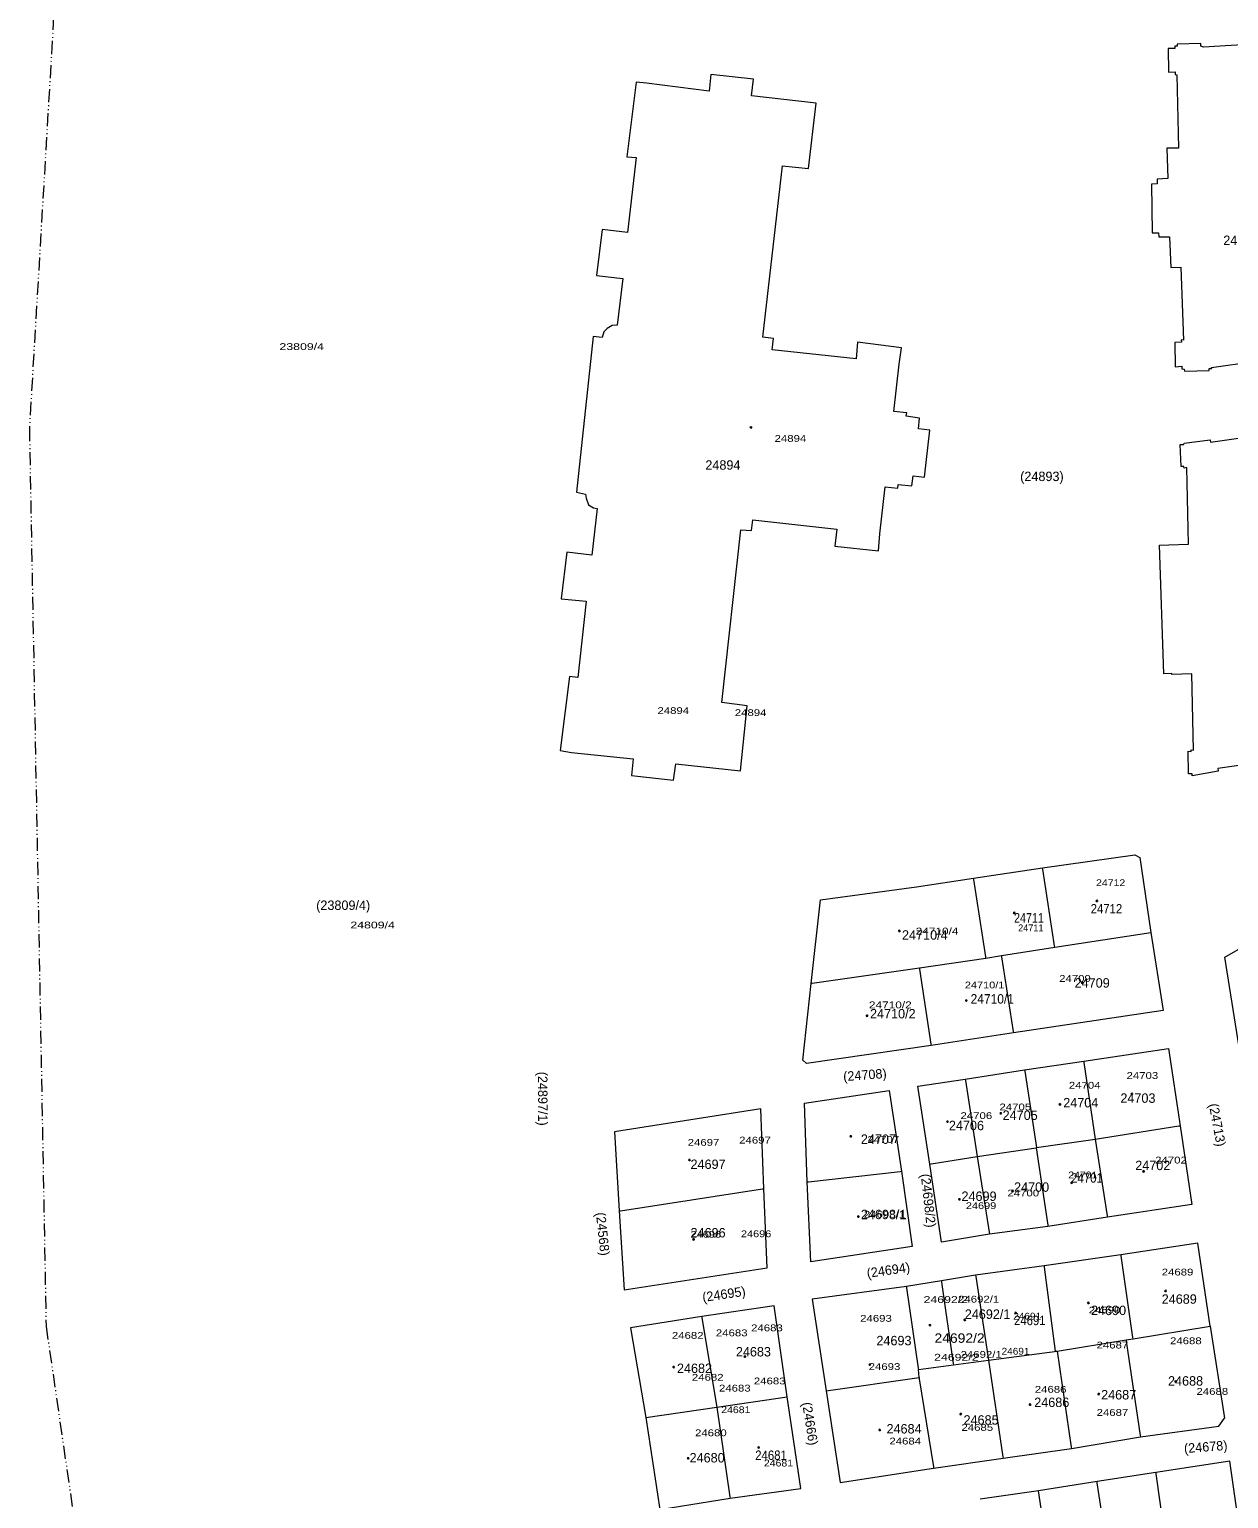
# Model space of a CAD drawing. Extents: x 649608 to 651081, y 237980 to 241202.
# Drawn here: x 649608 to 650066, y 239944 to 240505 of the extents above; entities that cross this region are included whole.
import ezdxf

# ---------------------------------------------------------------- set-up
doc = ezdxf.new("R2010")
doc.units = 0
doc.header["$PDMODE"] = 32
doc.header["$PDSIZE"] = 0.5
doc.linetypes.add('DASH_DOUBLE_DOT', pattern=[9.2, 5, -1.2, 0.3, -1.2, 0.3, -1.2])
for name, color, linetype in [('19', 7, 'Continuous'), ('20', 7, 'Continuous'), ('6', 7, 'Continuous')]:
    doc.layers.add(name, color=color, linetype=linetype)
for name, color, linetype, lineweight in [('3', 7, 'Continuous', 13), ('5', 7, 'Continuous', 13), ('52', 7, 'DASH_DOUBLE_DOT', 13)]:
    doc.layers.add(name, color=color, linetype=linetype, lineweight=lineweight)

msp = doc.modelspace()

# ---------------------------------------------------------------- linework, layer by layer
at = {"layer": '3'}
for p, q in [((649956.398, 240041.806), (649951.992, 240071.566)), ((649906.555, 240034.245), (649905.177, 240064.761)), ((649889.977, 240031.923), (649888.645, 240062.14)), ((650059.013, 240009.729), (650064.478, 239974.635))]:
    msp.add_line(p, q, dxfattribs=at)
for points in [[(650088.158, 240499.721), (650056.369, 240497.741), (650055.469, 240498.2), (650055.456, 240499.144), (650046.349, 240498.986), (650046.439, 240498.166), (650045.459, 240498.178), (650045.473, 240497.309), (650042.882, 240497.242), (650043.046, 240488.25), (650045.662, 240488.341), (650045.65, 240487.372), (650046.252, 240487.191), (650046.833, 240459.267), (650042.456, 240459.199), (650042.864, 240447.62), (650038.787, 240447.399), (650038.79, 240445.66), (650036.576, 240445.539), (650036.895, 240426.884), (650039.285, 240426.928), (650039.417, 240425.386), (650043.392, 240425.46), (650043.899, 240413.731), (650047.824, 240413.879), (650048.733, 240386.002), (650047.854, 240386.112), (650047.968, 240385.192), (650045.477, 240385.099), (650045.563, 240375.859), (650048.155, 240376), (650048.117, 240374.982), (650049.047, 240374.946), (650049.188, 240374.124), (650058.572, 240374.377), (650058.557, 240375.172), (650059.613, 240375.184), (650059.467, 240375.583), (650091.818, 240380.163)], [(649843.927, 240484.103), (649839.932, 240484.452), (649836.382, 240455.96), (649839.9, 240455.742), (649836.599, 240427.073), (649826.955, 240428.165), (649824.848, 240410.607), (649834.895, 240409.486), (649832.685, 240391.707), (649830.722, 240391.608), (649828.846, 240390.415), (649827.599, 240389.213), (649826.993, 240387.011), (649823.577, 240387.402), (649817.15, 240328.026), (649820.611, 240327.212), (649820.818, 240325.695), (649821.742, 240323.174), (649823.614, 240322.058), (649825.069, 240321.716), (649822.96, 240303.961), (649813.468, 240305.125), (649811.283, 240287.246), (649820.904, 240286.378), (649817.673, 240257.311), (649814.454, 240257.616), (649810.936, 240229.407), (649815.277, 240228.606)], [(649815.277, 240228.606), (649838.838, 240226.195), (649838.156, 240219.896), (649854.229, 240218.027), (649855.087, 240224.3), (649879.7, 240221.577), (649882.35, 240246.429), (649872.583, 240247.696), (649879.897, 240313.642), (649883.916, 240313.293), (649884.446, 240317.409), (649916.544, 240313.896), (649915.684, 240307.425), (649932.36, 240305.573), (649932.97, 240312.048), (649934.98, 240330.028), (649939.778, 240329.52), (649939.896, 240330.934), (649945.071, 240330.422), (649945.671, 240334.214), (649950.016, 240333.687), (649951.976, 240351.668), (649947.632, 240352.195), (649948.034, 240356.213), (649942.912, 240356.924), (649943.256, 240358.286), (649938.283, 240358.796), (649940.244, 240376.827), (649941.177, 240383.049), (649924.429, 240385.224), (649923.897, 240378.898), (649891.821, 240382.237), (649892.404, 240386.576), (649888.211, 240387.126), (649895.744, 240452.523), (649905.716, 240451.452), (649908.618, 240476.375), (649883.905, 240479.198), (649884.664, 240485.571), (649868.489, 240487.342), (649867.756, 240481.018), (649843.927, 240484.103)], [(650105.869, 240228.782), (650061.877, 240222.463), (650061.965, 240221.468), (650052.084, 240219.731), (650052.094, 240220.501), (650050.736, 240220.493), (650050.592, 240229.089), (650051.722, 240229), (650051.73, 240229.645), (650052.659, 240229.509), (650051.942, 240258.626), (650044.343, 240258.35), (650044.323, 240258.723), (650041.229, 240258.688), (650039.63, 240307.785), (650043.253, 240307.912), (650050.676, 240308.19), (650050.085, 240337.331), (650049.078, 240337.194), (650048.984, 240337.767), (650047.853, 240337.781), (650047.506, 240346.23), (650048.939, 240346.187), (650048.995, 240346.683), (650058.996, 240347.971), (650059.084, 240347.002), (650093.981, 240352.071)], [(649995.006, 240184.644), (650030.254, 240189.635), (650032.177, 240188.567), (650036.32, 240159.878), (650041.004, 240130.164)], [(649906.653, 240140.492), (649910.246, 240172.386), (649946.953, 240177.407), (649968.698, 240180.608), (649995.006, 240184.644)], [(650072.262, 240101.751), (650064.598, 240150.503), (650083.395, 240161.316), (650125.86, 240128.041)], [(649952.457, 240116.812), (649904.887, 240109.892), (649903.57, 240111.225), (649906.653, 240140.492)], [(650041.004, 240130.164), (649983.906, 240121.652), (649952.457, 240116.812)], [(650010.731, 240110.78), (650043.035, 240115.634), (650047.521, 240086.196)], [(649951.992, 240071.566), (649947.358, 240101.23), (649965.5, 240103.905), (649988.13, 240107.467), (650010.731, 240110.78)], [(649905.177, 240064.761), (649904.119, 240094.777), (649936.498, 240099.58), (649941.168, 240068.798), (649945.286, 240040.135), (649906.555, 240034.245)], [(649888.645, 240062.14), (649887.493, 240092.654), (649831.699, 240083.851), (649833.51, 240053.653), (649835.32, 240023.503), (649889.977, 240031.923)], [(650047.521, 240086.196), (650051.923, 240056.163), (650019.771, 240051.332), (649997.04, 240047.771), (649974.745, 240044.777), (649956.398, 240041.806)], [(650059.013, 240009.729), (650054.253, 240041.356), (650024.873, 240036.986), (649995.62, 240032.714), (649969.469, 240029.197), (649956.414, 240027.029), (649943.032, 240024.84), (649907.081, 240019.957), (649912.382, 239985.056)], [(649897.559, 239982.761), (649892.562, 240017.41), (649864.972, 240013.365), (649837.78, 240009.017), (649843.637, 239974.808)], [(649912.382, 239985.056), (649917.768, 239950.018), (649953.446, 239955.524), (649979.947, 239959.352), (650006.063, 239963.057), (650032.338, 239967.416)], [(649875.782, 239944.051), (649902.818, 239947.775), (649897.559, 239982.761)], [(649843.637, 239974.808), (649849.023, 239939.796), (649875.782, 239944.051)], [(650032.338, 239967.416), (650062.313, 239971.548), (650064.478, 239974.635)], [(650071.051, 239926.074), (650066.514, 239958.205), (650038.223, 239953.835), (650015.835, 239950.432), (649993.523, 239946.827), (649971.163, 239943.727)]]:
    msp.add_lwpolyline(points, dxfattribs=at)
at = {"layer": '5'}
msp.add_line((649992.689, 240077.854), (650015.088, 240081.07), dxfattribs=at)
for points in [[(649973.423, 240150.198), (649973.345, 240150.698), (649968.776, 240180.108), (649968.698, 240180.608)], [(649999.707, 240154.334), (649999.629, 240154.834), (649995.084, 240184.144), (649995.006, 240184.644)], [(649906.653, 240140.492), (649907.153, 240140.564), (649948.024, 240146.423), (649973.423, 240150.198), (649979.32, 240151.141), (649999.707, 240154.334), (650036.32, 240159.878)], [(649979.32, 240151.141), (649979.398, 240150.641), (649983.828, 240122.152), (649983.906, 240121.652)], [(649948.024, 240146.423), (649948.099, 240145.923), (649952.382, 240117.312), (649952.457, 240116.812)], [(650010.731, 240110.78), (650010.804, 240110.28), (650015.088, 240081.07)], [(649965.5, 240103.905), (649965.577, 240103.405), (649970.061, 240074.466), (649974.745, 240044.777)], [(649988.13, 240107.467), (649988.207, 240106.967), (649992.689, 240077.854), (649992.537, 240077.806)], [(650015.088, 240081.07), (650047.021, 240086.117), (650047.521, 240086.196)], [(650015.088, 240081.07), (650019.692, 240051.832), (650019.771, 240051.332)], [(649951.992, 240071.566), (649952.492, 240071.646), (649970.061, 240074.466), (649992.537, 240077.806)], [(649992.537, 240077.806), (649996.965, 240048.271), (649997.04, 240047.771)], [(649905.177, 240064.761), (649905.677, 240064.817), (649940.668, 240068.742), (649941.168, 240068.798)], [(649833.51, 240053.653), (649834.01, 240053.73), (649888.145, 240062.063), (649888.645, 240062.14)], [(650029.577, 240004.912), (650029.504, 240005.412), (650024.946, 240036.486), (650024.873, 240036.986)], [(649969.469, 240029.197), (649969.544, 240028.697), (649974.346, 239996.761)], [(649995.62, 240032.714), (649995.685, 240032.214), (649999.84, 240000.15), (650000.595, 240000.215), (650026.856, 240004.5), (650029.577, 240004.912), (650059.013, 240009.729)], [(649943.032, 240024.84), (649943.104, 240024.34), (649947.545, 239993.636), (649947.617, 239993.136)], [(649956.414, 240027.029), (649956.486, 240026.529), (649960.961, 239995.461), (649961.033, 239994.961)], [(649864.972, 240013.365), (649865.054, 240012.865), (649870.675, 239978.759)], [(650026.856, 240004.5), (650026.93, 240004), (650032.264, 239967.916), (650032.338, 239967.416)], [(649912.382, 239985.056), (649947.878, 239990.159), (649947.617, 239993.136), (649961.033, 239994.961), (649974.346, 239996.761), (650000.595, 240000.215)], [(649974.346, 239996.761), (649979.872, 239959.852), (649979.947, 239959.352)], [(650000.595, 240000.215), (650005.989, 239963.557), (650006.063, 239963.057)], [(649947.878, 239990.159), (649947.958, 239989.659), (649953.366, 239956.024), (649953.446, 239955.524)], [(649843.637, 239974.808), (649870.675, 239978.759), (649897.559, 239982.761)], [(649870.675, 239978.759), (649875.708, 239944.551), (649875.782, 239944.051)], [(650038.223, 239953.835), (650038.293, 239953.335), (650042.709, 239921.779)], [(649997.799, 239917.622), (649997.726, 239918.122), (649993.523, 239946.827)], [(650020.705, 239918.5), (650015.911, 239949.932), (650015.835, 239950.432)]]:
    msp.add_lwpolyline(points, dxfattribs=at)
at = {"layer": '52'}
msp.add_lwpolyline([(649701.481, 241202.319), (649640.936, 240904.262), (649608.393, 240352.424), (649614.771, 240009.578), (649631.5, 239894.49), (649662.347, 239679.564), (649715.192, 239448.546), (649776.71, 239295.263), (649918.979, 238940.568), (649995.713, 238777.318), (650020.382, 238724.355), (650126.69, 238550.145), (650295.37, 238327.169), (650466.153, 238100.489), (650557.889, 237992.529), (650568.158, 237979.989)], dxfattribs=at)
at = {"layer": '6'}
for p in [(649883.75, 240352.684), (650015.771, 240171.984), (649984.212, 240167.421), (649940.364, 240160.55), (650010.133, 240140.765), (649965.938, 240133.976), (649928.056, 240128.157), (650029.111, 240098.352), (649979.087, 240090.966), (650001.65, 240094.317), (649958.736, 240087.735), (649921.851, 240082.17), (649860.285, 240073.153), (650033.551, 240068.764), (650006.127, 240064.42), (649963.309, 240058.136), (649983.576, 240061.291), (649924.713, 240051.521), (649861.828, 240042.821), (650012.514, 240018.568), (650041.95, 240023.134), (649965.305, 240012.079), (649984.796, 240014.737), (649952.011, 240010.082), (649881.42, 239998.084), (649854.243, 239994.086), (649929.109, 239995.002), (650045.759, 239988.572), (649990.245, 239979.783), (650016.466, 239983.778), (649963.782, 239976.142), (649932.894, 239970.088), (649886.701, 239963.406), (649859.784, 239959.277)]:
    msp.add_point(p, dxfattribs=at)

# ---------------------------------------------------------------- texts
at = {"layer": '19'}
for s, p in [('24898', (650063.974, 240422.307)), ('24894', (649866.345, 240336.546)), ('(24893)', (649986.478, 240332.212)), ('(23809/4)', (649717.833, 240168.541)), ('24710/4', (649941.383, 240157.186)), ('24709', (650007.259, 240138.901)), ('24710/2', (649929.169, 240127.147)), ('24704', (650002.897, 240093.19)), ('24703', (650024.71, 240094.932)), ('24705', (649979.775, 240088.402)), ('24706', (649959.272, 240084.484)), ('24707', (649925.68, 240079.259)), ('24697', (649860.676, 240069.682)), ('24702', (650030.382, 240069.247)), ('24700', (649984.138, 240060.975)), ('24699', (649964.07, 240057.493)), ('24698/1', (649925.679, 240050.527)), ('24696', (649860.676, 240043.562)), ('24689', (650040.479, 240018.254)), ('24692/1', (649965.334, 240012.486)), ('24690', (650013.503, 240013.928)), ('24683', (649877.981, 239998.147)), ('24693', (649931.614, 240002.391)), ('24682', (649855.505, 239991.816)), ('24688', (650042.888, 239987.009)), ('24687', (650017.359, 239981.722)), ('24686', (649991.828, 239978.838)), ('24685', (649964.852, 239972.108)), ('24684', (649935.467, 239968.743)), ('24680', (649860.321, 239957.687))]:
    msp.add_text(s, height=3.6, dxfattribs=at).set_placement(p)
for s, width, p in [('24712', 0.9, (650013.367, 240167.198)), ('24711', 0.85, (649984.138, 240163.716)), ('24710/1', 0.95, (649967.56, 240132.807)), ('24701', 0.9, (650005.951, 240064.458)), ('24691', 0.9, (649984.12, 240010.082)), ('24692/2', 1.1, (649953.772, 240003.353)), ('24681', 0.9, (649885.371, 239958.649))]:
    msp.add_text(s, height=3.6, dxfattribs=dict(at, width=width)).set_placement(p)
for s, rotation, p in [('(24708)', 4.374, (649919.087, 240103.178)), ('(24897/1)', 270.218, (649802.464, 240106.793)), ('(24713)', 280.524, (650058.445, 240094.345)), ('(24698/2)', 276.361, (649948.51, 240067.662)), ('(24568)', 276.03, (649824.557, 240052.949)), ('(24694)', 8.362, (649928.209, 240028.104)), ('(24695)', 8.362, (649865.474, 240018.925)), ('(24666)', 279.01, (649903.256, 239980.398)), ('(24678)', 4.326, (650049.13, 239961.241))]:
    msp.add_text(s, height=3.6, rotation=rotation, dxfattribs=at).set_placement(p)
at = {"layer": '20'}
for s, width, p in [('23809/4', 1.35, (649703.827, 240382.237)), ('24894', 1.25, (649892.749, 240347.175)), ('24894', 1.25, (649848.049, 240243.324)), ('24894', 1.25, (649877.573, 240242.537)), ('24712', 1.15, (650015.434, 240177.646)), ('24809/4', 1.35, (649730.884, 240161.495)), ('24710/4', 1.3, (649946.581, 240159.158)), ('24710/1', 1.2, (649965.358, 240138.6)), ('24709', 1.25, (650001.344, 240141.083)), ('24710/2', 1.3, (649928.749, 240131.011)), ('24704', 1.25, (650005.057, 240100.331)), ('24703', 1.25, (650027.069, 240104.056)), ('24706', 1.25, (649963.707, 240088.741)), ('24705', 1.25, (649978.562, 240092.052)), ('24697', 1.25, (649859.598, 240078.527)), ('24697', 1.25, (649879.237, 240079.385)), ('24707', 1.25, (649928.181, 240079.656)), ('24702', 1.25, (650037.983, 240071.771)), ('24701', 1.15, (650004.802, 240066.114)), ('24700', 1.25, (649981.605, 240059.215)), ('24698/1', 1.25, (649926.839, 240051.096)), ('24699', 1.2, (649965.74, 240054.386)), ('24696', 1.2, (649860.708, 240043.444)), ('24696', 1.2, (649879.908, 240043.651)), ('24689', 1.25, (650040.479, 240029.042)), ('24692/2', 1.35, (649949.607, 240018.556)), ('24692/1', 1.25, (649962.769, 240018.694)), ('24693', 1.25, (649925.406, 240011.381)), ('24691', 1.1, (649983.826, 240012.209)), ('24690', 1.25, (650012.628, 240014.555)), ('24682', 1.25, (649853.564, 240004.867)), ('24683', 1.25, (649870.356, 240005.85)), ('24683', 1.25, (649883.793, 240007.752)), ('24691', 1.1, (649979.382, 239998.83)), ('24687', 1.25, (650015.618, 240001.183)), ('24688', 1.25, (650043.653, 240002.827)), ('24693', 1.25, (649928.66, 239992.977)), ('24692/2', 1.35, (649953.632, 239996.535)), ('24692/1', 1.25, (649963.735, 239997.62)), ('24682', 1.25, (649861.2, 239988.887)), ('24683', 1.25, (649884.851, 239987.492)), ('24683', 1.25, (649871.536, 239984.74)), ('24686', 1.25, (649992.05, 239984.294)), ('24688', 1.25, (650053.748, 239983.49)), ('24681', 1.15, (649872.399, 239976.511)), ('24687', 1.25, (650015.633, 239975.463)), ('24680', 1.25, (649862.399, 239967.697)), ('24685', 1.25, (649964.062, 239969.756)), ('24684', 1.25, (649936.569, 239964.545)), ('24681', 1.15, (649888.685, 239956.153))]:
    msp.add_text(s, height=2.6, dxfattribs=dict(at, width=width)).set_placement(p)
msp.add_text('24711', height=2.6, dxfattribs=at).set_placement((649985.701, 240160.399))

doc.saveas('drawing.dxf')
